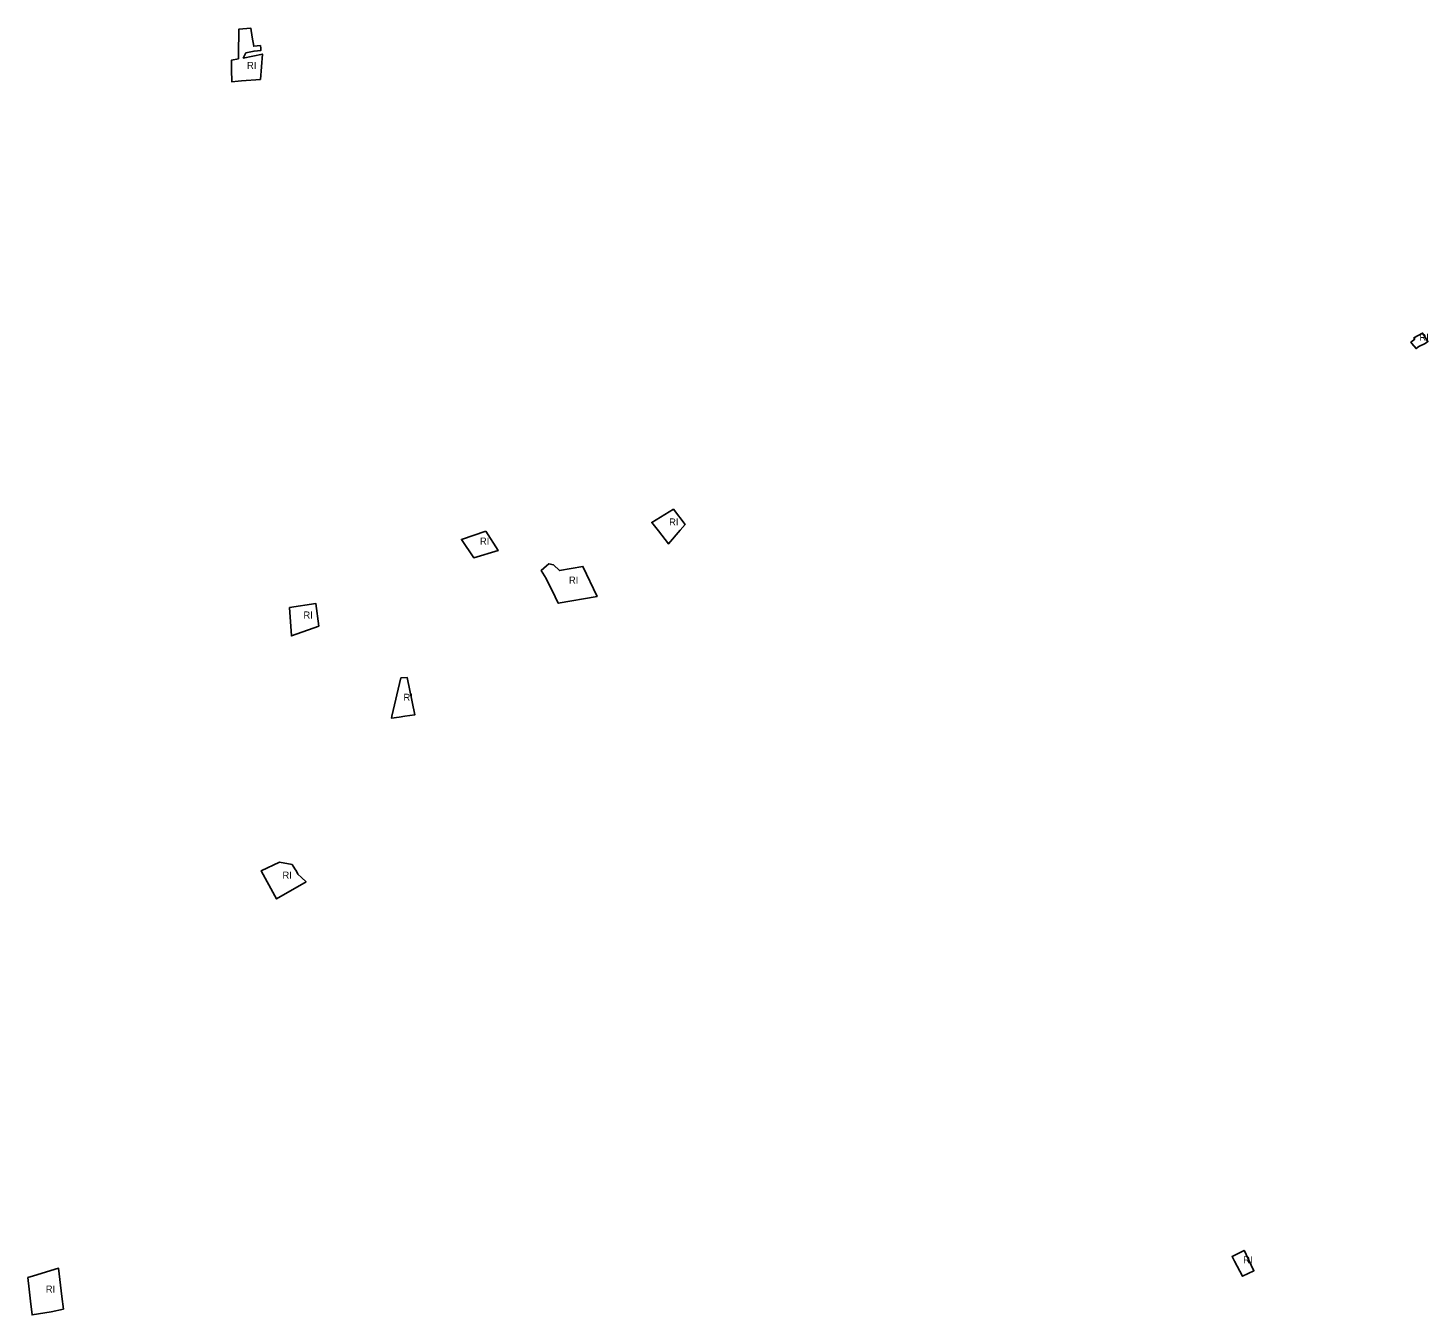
# Model space of a CAD drawing. Extents: x -477010 to -466219, y -1158799 to -1150161.
# Drawn here: x -473623 to -471832, y -1156660 to -1155013 of the extents above; entities that cross this region are included whole.
import ezdxf

# ---------------------------------------------------------------- set-up
doc = ezdxf.new("R2010")
doc.units = 0
doc.layers.add('19', color=7, linetype='Continuous')

msp = doc.modelspace()

# ---------------------------------------------------------------- linework, layer by layer
at = {"layer": '19'}
for points in [[(-473325.56, -1155038.54), (-473325.27, -1155041.62), (-473333.93, -1155042.44), (-473344.49, -1155044.71), (-473347.8, -1155051.4), (-473323.31, -1155046.21), (-473325.91, -1155078.7), (-473350.03, -1155080.69), (-473354.31, -1155080.93), (-473362.65, -1155081.62), (-473362.77, -1155066.06), (-473362.79, -1155063.71), (-473362.87, -1155053.96), (-473354.01, -1155052.35), (-473353.96, -1155047.15), (-473353.64, -1155014.55), (-473338.29, -1155012.91), (-473336.36, -1155024.64), (-473334.51, -1155036.27), (-473325.85, -1155035.45)], [(-471843.85, -1155420.2), (-471847.25, -1155422.99), (-471852.64, -1155416.42), (-471853.91, -1155414.88), (-471850.51, -1155412.09), (-471848.96, -1155410.82), (-471850.21, -1155409.3), (-471839.03, -1155403.27), (-471837.38, -1155405.91), (-471832.19, -1155414.19), (-471835.78, -1155416.44)], [(-472788.76, -1155655.34), (-472803.73, -1155673.01), (-472816.82, -1155656.3), (-472825.33, -1155645.43), (-472797.55, -1155628.71), (-472782.65, -1155648.13)], [(-473037.43, -1155656.46), (-473021.935, -1155681.52), (-473053.082, -1155690.695), (-473068.761, -1155667.127)], [(-472960.02, -1155700.99), (-472956.94, -1155698.28), (-472951.01, -1155699.76), (-472943.29, -1155707.06), (-472913.24, -1155701.82), (-472895.22, -1155740.09), (-472944.94, -1155748.81), (-472949.03, -1155740.56), (-472960.52, -1155717.37), (-472966.66, -1155706.82)], [(-473288.84, -1155754.46), (-473255.1, -1155749.21), (-473251.31, -1155778.13), (-473286.17, -1155790.77)], [(-473157.69, -1155893.47), (-473146.26, -1155844.47), (-473138.32, -1155843.68), (-473128.44, -1155891.76), (-473141.27, -1155893.5), (-473148.56, -1155894.48), (-473158.23, -1155895.79)], [(-473285.38, -1156083.31), (-473281.71, -1156088.8), (-473279.87, -1156091.65), (-473277.95, -1156095.59), (-473273.37, -1156099.84), (-473267.56, -1156105.21), (-473305.19, -1156127.09), (-473307.54, -1156123.05), (-473324.83, -1156091.24), (-473301.65, -1156080.24)], [(-472066.88, -1156577.62), (-472064.73, -1156581.94), (-472054.9, -1156602.89), (-472069.55, -1156610.04), (-472079.58, -1156590.58), (-472082.65, -1156584.62), (-472067.29, -1156576.79)], [(-473593.73, -1156655.39), (-473618.073, -1156659.521), (-473620, -1156641.85), (-473621.686, -1156626.392), (-473623.29, -1156611.685), (-473616.46, -1156609.6), (-473584.23, -1156599.77), (-473579.97, -1156635.98), (-473578.081, -1156652.036)]]:
    msp.add_lwpolyline(points, close=True, dxfattribs=at)

# ---------------------------------------------------------------- texts
for p in [(-473343.025, -1155065.254), (-471843.012, -1155413.123), (-472802.987, -1155649.413), (-473045.149, -1155673.844), (-472931.225, -1155723.802), (-473270.882, -1155768.439), (-473142.863, -1155873.717), (-473297.709, -1156101.236), (-472068.56, -1156593.434), (-473600.534, -1156630.822)]:
    msp.add_text('RI', height=9, dxfattribs=at).set_placement(p)

doc.saveas('drawing.dxf')
